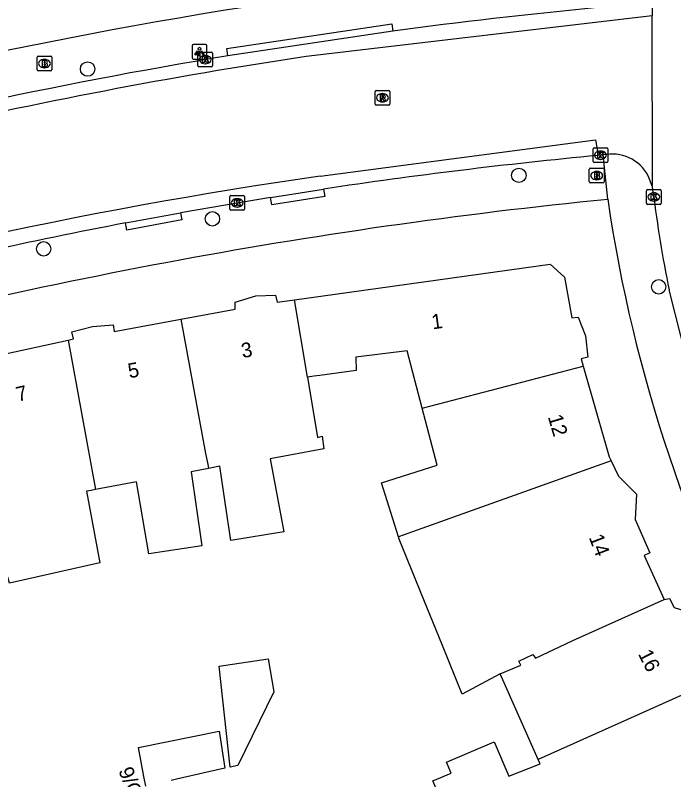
# Model space of a CAD drawing. Extents: x 160356 to 161355, y 381727 to 382845.
# Drawn here: x 161242.7 to 161287.4, y 382329.8 to 382381.7 of the extents above; entities that cross this region are included whole.
import ezdxf

# ---------------------------------------------------------------- set-up
doc = ezdxf.new("R2010")
doc.units = 0
for name, color, linetype in [('IMGEO_Boom', 7, 'Continuous'), ('IMGEO_Brandkraan', 7, 'Continuous'), ('IMGEO_Kolk', 7, 'Continuous'), ('IMGEO_Lichtpunt', 7, 'Continuous'), ('IMGEO_Pand', 7, 'Continuous'), ('IMGEO_Pand_nummerreeks', 7, 'Continuous'), ('IMGEO_Rijbaan_lokaal_open', 7, 'Continuous'), ('IMGEO_Rioolput', 7, 'Continuous'), ('IMGEO_Voetpad_open', 7, 'Continuous')]:
    doc.layers.add(name, color=color, linetype=linetype)

msp = doc.modelspace()

# ---------------------------------------------------------------- linework, layer by layer
at = {"layer": 'IMGEO_Boom'}
for centre in [(161247.634, 382378.019), (161276.877, 382370.816), (161256.1, 382367.867), (161244.655, 382365.834), (161286.356, 382363.259)]:
    msp.add_circle(centre, 0.489, dxfattribs=at)
at = {"layer": 'IMGEO_Brandkraan'}
for p, q in [((161244.282, 382378.894), (161245.134, 382378.894)), ((161244.207, 382377.968), (161244.207, 382378.82)), ((161244.695, 382378.674), (161244.72, 382378.674)), ((161245.208, 382378.82), (161245.208, 382377.968)), ((161245.134, 382377.894), (161244.282, 382377.894)), ((161244.718, 382378.114), (161244.693, 382378.114)), ((161281.654, 382370.372), (161281.654, 382371.224)), ((161281.729, 382371.298), (161282.581, 382371.298)), ((161282.655, 382371.224), (161282.655, 382370.372)), ((161282.142, 382371.078), (161282.167, 382371.078)), ((161282.581, 382370.298), (161281.729, 382370.298)), ((161282.165, 382370.518), (161282.14, 382370.518))]:
    msp.add_line(p, q, dxfattribs=at)
for points in [[(161244.282, 382378.894), (161245.134, 382378.894)], [(161244.207, 382377.968), (161244.207, 382378.82)], [(161244.555, 382378.594), (161244.555, 382378.194), (161244.768, 382378.194)], [(161244.786, 382378.594), (161244.555, 382378.594)], [(161244.734, 382378.513), (161244.68, 382378.513), (161244.68, 382378.437)], [(161244.68, 382378.437), (161244.733, 382378.437)], [(161244.742, 382378.361), (161244.68, 382378.361), (161244.68, 382378.28)], [(161245.208, 382378.82), (161245.208, 382377.968)], [(161245.134, 382377.894), (161244.282, 382377.894)], [(161244.68, 382378.28), (161244.742, 382378.28)], [(161281.654, 382370.372), (161281.654, 382371.224)], [(161281.729, 382371.298), (161282.581, 382371.298)], [(161282.655, 382371.224), (161282.655, 382370.372)], [(161282.002, 382370.998), (161282.002, 382370.598), (161282.215, 382370.598)], [(161282.233, 382370.998), (161282.002, 382370.998)], [(161282.181, 382370.917), (161282.127, 382370.917), (161282.127, 382370.841)], [(161282.127, 382370.841), (161282.18, 382370.841)], [(161282.189, 382370.765), (161282.127, 382370.765), (161282.127, 382370.684)], [(161282.127, 382370.684), (161282.189, 382370.684)], [(161282.581, 382370.298), (161281.729, 382370.298)]]:
    msp.add_lwpolyline(points, dxfattribs=at)
for centre, radius, start, end in [((161244.284, 382378.818), 0.0765, 91.552, 178.448), ((161244.284, 382378.818), 0.0765, 91.552, 178.448), ((161245.132, 382378.818), 0.0765, 1.552, 88.448), ((161245.132, 382378.818), 0.0765, 1.552, 88.448), ((161244.735, 382378.475), 0.0379, 267.8285, 90.9355), ((161244.743, 382378.32), 0.0404, 269.8759, 90.5077), ((161244.79, 382378.449), 0.145, 59.4692, 91.5367), ((161244.815, 382378.496), 0.0922, 285.5137, 58.1501), ((161244.82, 382378.304), 0.105, 301.3115, 78.989), ((161244.284, 382377.97), 0.0765, 181.552, 268.448), ((161244.284, 382377.97), 0.0765, 181.552, 268.448), ((161244.774, 382378.445), 0.251, 268.6676, 293.5347), ((161245.132, 382377.97), 0.0765, 271.552, 358.448), ((161245.132, 382377.97), 0.0765, 271.552, 358.448), ((161281.731, 382371.222), 0.0765, 91.552, 178.448), ((161281.731, 382371.222), 0.0765, 91.552, 178.448), ((161282.579, 382371.222), 0.0765, 1.552, 88.448), ((161282.579, 382371.222), 0.0765, 1.552, 88.448), ((161282.182, 382370.879), 0.0379, 267.8285, 90.9355), ((161282.19, 382370.724), 0.0404, 269.8759, 90.5077), ((161282.221, 382370.849), 0.251, 268.6676, 293.5347), ((161282.237, 382370.853), 0.145, 59.4692, 91.5367), ((161282.262, 382370.9), 0.0922, 285.5137, 58.1501), ((161282.267, 382370.708), 0.105, 301.3115, 78.989), ((161281.731, 382370.374), 0.0765, 181.552, 268.448), ((161281.731, 382370.374), 0.0765, 181.552, 268.448), ((161282.579, 382370.374), 0.0765, 271.552, 358.448), ((161282.579, 382370.374), 0.0765, 271.552, 358.448)]:
    msp.add_arc(centre, radius, start, end, dxfattribs=at)
for centre, major_axis, ratio, start_param, end_param in [((161244.694, 382378.394), (-0.387, 0.002), 0.722429, 4.712389, 7.853982), ((161244.719, 382378.394), (-0.39, 0.002), 0.717154, 1.570796, 4.712389), ((161282.141, 382370.798), (-0.387, 0.002), 0.722429, 4.712389, 7.853982), ((161282.166, 382370.798), (-0.39, 0.002), 0.717154, 1.570796, 4.712389)]:
    msp.add_ellipse(centre, major_axis=major_axis, ratio=ratio, start_param=start_param, end_param=end_param, dxfattribs=at)
at = {"layer": 'IMGEO_Kolk'}
for p, q in [((161255.111, 382378.237), (161255.111, 382379.089)), ((161255.186, 382379.163), (161256.038, 382379.163)), ((161255.599, 382378.943), (161255.624, 382378.943)), ((161256.112, 382379.089), (161256.112, 382378.237)), ((161255.622, 382378.383), (161255.597, 382378.383)), ((161256.038, 382378.163), (161255.186, 382378.163)), ((161281.982, 382372.68), (161282.834, 382372.68)), ((161281.907, 382371.754), (161281.907, 382372.606)), ((161282.395, 382372.46), (161282.42, 382372.46)), ((161282.908, 382372.606), (161282.908, 382371.754)), ((161282.834, 382371.68), (161281.982, 382371.68)), ((161282.418, 382371.9), (161282.393, 382371.9)), ((161285.527, 382368.924), (161285.527, 382369.776)), ((161285.602, 382369.85), (161286.454, 382369.85)), ((161286.015, 382369.63), (161286.04, 382369.63)), ((161286.528, 382369.776), (161286.528, 382368.924)), ((161257.279, 382368.523), (161257.279, 382369.375)), ((161257.354, 382369.449), (161258.206, 382369.449)), ((161257.767, 382369.229), (161257.792, 382369.229)), ((161258.28, 382369.375), (161258.28, 382368.523)), ((161286.038, 382369.07), (161286.013, 382369.07)), ((161257.79, 382368.669), (161257.765, 382368.669)), ((161286.454, 382368.85), (161285.602, 382368.85)), ((161258.206, 382368.449), (161257.354, 382368.449))]:
    msp.add_line(p, q, dxfattribs=at)
for points in [[(161255.111, 382378.237), (161255.111, 382379.089)], [(161255.186, 382379.163), (161256.038, 382379.163)], [(161256.112, 382379.089), (161256.112, 382378.237)], [(161255.432, 382378.863), (161255.555, 382378.863), (161255.555, 382378.712), (161255.685, 382378.863), (161255.849, 382378.863), (161255.703, 382378.712), (161255.856, 382378.463), (161255.704, 382378.463), (161255.619, 382378.627), (161255.555, 382378.56), (161255.555, 382378.463), (161255.432, 382378.463), (161255.432, 382378.863)], [(161256.038, 382378.163), (161255.186, 382378.163)], [(161281.982, 382372.68), (161282.834, 382372.68)], [(161281.907, 382371.754), (161281.907, 382372.606)], [(161282.228, 382372.38), (161282.351, 382372.38), (161282.351, 382372.229), (161282.481, 382372.38), (161282.645, 382372.38), (161282.499, 382372.229), (161282.652, 382371.98), (161282.5, 382371.98), (161282.415, 382372.144), (161282.351, 382372.077), (161282.351, 382371.98), (161282.228, 382371.98), (161282.228, 382372.38)], [(161282.908, 382372.606), (161282.908, 382371.754)], [(161282.834, 382371.68), (161281.982, 382371.68)], [(161285.527, 382368.924), (161285.527, 382369.776)], [(161285.602, 382369.85), (161286.454, 382369.85)], [(161285.848, 382369.55), (161285.971, 382369.55), (161285.971, 382369.399), (161286.101, 382369.55), (161286.265, 382369.55), (161286.119, 382369.399), (161286.272, 382369.15), (161286.12, 382369.15), (161286.035, 382369.314), (161285.971, 382369.247), (161285.971, 382369.15), (161285.848, 382369.15), (161285.848, 382369.55)], [(161286.528, 382369.776), (161286.528, 382368.924)], [(161257.279, 382368.523), (161257.279, 382369.375)], [(161257.354, 382369.449), (161258.206, 382369.449)], [(161257.6, 382369.149), (161257.723, 382369.149), (161257.723, 382368.998), (161257.853, 382369.149), (161258.017, 382369.149), (161257.871, 382368.998), (161258.024, 382368.749), (161257.872, 382368.749), (161257.787, 382368.913), (161257.723, 382368.846), (161257.723, 382368.749), (161257.6, 382368.749), (161257.6, 382369.149)], [(161258.28, 382369.375), (161258.28, 382368.523)], [(161286.454, 382368.85), (161285.602, 382368.85)], [(161258.206, 382368.449), (161257.354, 382368.449)]]:
    msp.add_lwpolyline(points, dxfattribs=at)
for centre, start, end in [((161255.188, 382379.087), 91.552, 178.448), ((161255.188, 382379.087), 91.552, 178.448), ((161256.036, 382379.087), 1.552, 88.448), ((161256.036, 382379.087), 1.552, 88.448), ((161255.188, 382378.239), 181.552, 268.448), ((161255.188, 382378.239), 181.552, 268.448), ((161256.036, 382378.239), 271.552, 358.448), ((161256.036, 382378.239), 271.552, 358.448), ((161281.984, 382372.604), 91.552, 178.448), ((161281.984, 382372.604), 91.552, 178.448), ((161282.832, 382372.604), 1.552, 88.448), ((161282.832, 382372.604), 1.552, 88.448), ((161281.984, 382371.756), 181.552, 268.448), ((161281.984, 382371.756), 181.552, 268.448), ((161282.832, 382371.756), 271.552, 358.448), ((161282.832, 382371.756), 271.552, 358.448), ((161285.604, 382369.774), 91.552, 178.448), ((161285.604, 382369.774), 91.552, 178.448), ((161286.452, 382369.774), 1.552, 88.448), ((161286.452, 382369.774), 1.552, 88.448), ((161257.356, 382369.373), 91.552, 178.448), ((161257.356, 382369.373), 91.552, 178.448), ((161258.204, 382369.373), 1.552, 88.448), ((161258.204, 382369.373), 1.552, 88.448), ((161257.356, 382368.525), 181.552, 268.448), ((161257.356, 382368.525), 181.552, 268.448), ((161258.204, 382368.525), 271.552, 358.448), ((161258.204, 382368.525), 271.552, 358.448), ((161285.604, 382368.926), 181.552, 268.448), ((161285.604, 382368.926), 181.552, 268.448), ((161286.452, 382368.926), 271.552, 358.448), ((161286.452, 382368.926), 271.552, 358.448)]:
    msp.add_arc(centre, 0.0765, start, end, dxfattribs=at)
for centre, major_axis, ratio, start_param, end_param in [((161255.598, 382378.663), (-0.387, 0.002), 0.722429, 4.712389, 7.853982), ((161255.623, 382378.663), (-0.39, 0.002), 0.717154, 1.570796, 4.712389), ((161282.394, 382372.18), (-0.387, 0.002), 0.722429, 4.712389, 7.853982), ((161282.419, 382372.18), (-0.39, 0.002), 0.717154, 1.570796, 4.712389), ((161286.014, 382369.35), (-0.387, 0.002), 0.722429, 4.712389, 7.853982), ((161286.039, 382369.35), (-0.39, 0.002), 0.717154, 1.570796, 4.712389), ((161257.766, 382368.949), (-0.387, 0.002), 0.722429, 4.712389, 7.853982), ((161257.791, 382368.949), (-0.39, 0.002), 0.717154, 1.570796, 4.712389)]:
    msp.add_ellipse(centre, major_axis=major_axis, ratio=ratio, start_param=start_param, end_param=end_param, dxfattribs=at)
at = {"layer": 'IMGEO_Lichtpunt'}
for p, q in [((161254.722, 382379.6), (161254.722, 382378.793)), ((161254.722, 382379.6), (161254.722, 382378.793)), ((161255.624, 382379.695), (161254.816, 382379.695)), ((161255.624, 382379.695), (161254.816, 382379.695)), ((161255.718, 382378.793), (161255.718, 382379.6)), ((161255.718, 382378.793), (161255.718, 382379.6)), ((161254.816, 382378.699), (161255.624, 382378.699)), ((161254.816, 382378.699), (161255.624, 382378.699))]:
    msp.add_line(p, q, dxfattribs=at)
for points in [[(161255.096, 382379.264), (161255.135, 382379.236), (161254.947, 382378.974), (161254.909, 382379.001), (161255.096, 382379.264)], [(161255.198, 382379.216), (161255.245, 382379.216), (161255.245, 382378.894), (161255.198, 382378.894), (161255.198, 382379.216)], [(161255.308, 382379.236), (161255.346, 382379.263), (161255.533, 382379.001), (161255.494, 382378.973), (161255.308, 382379.236)]]:
    msp.add_lwpolyline(points, dxfattribs=at)
msp.add_circle((161255.221, 382379.398), 0.0994, dxfattribs=at)
for centre, start, end in [((161254.816, 382379.6), 90, 180), ((161254.816, 382379.6), 90, 180), ((161255.624, 382379.6), 0, 90), ((161255.624, 382379.6), 0, 90), ((161254.816, 382378.793), 180, 270), ((161254.816, 382378.793), 180, 270), ((161255.624, 382378.793), 270, 0), ((161255.624, 382378.793), 270, 360)]:
    msp.add_arc(centre, 0.0946, start, end, dxfattribs=at)
at = {"layer": 'IMGEO_Pand'}
for points in [[(161261.673, 382362.386), (161278.988, 382364.789), (161279.97, 382363.923), (161280.478, 382361.165), (161280.908, 382361.206), (161281.391, 382359.928), (161281.556, 382358.489), (161281.096, 382358.387), (161281.244, 382357.87)], [(161253.95, 382361.072), (161257.643, 382361.754), (161257.632, 382362.223), (161259.04, 382362.648), (161260.369, 382362.702), (161260.491, 382362.222), (161261.673, 382362.386)], [(161262.547, 382357.134), (161261.673, 382362.386)], [(161246.318, 382359.651), (161246.683, 382359.73), (161246.561, 382360.209), (161247.969, 382360.574), (161249.369, 382360.678), (161249.43, 382360.238), (161253.95, 382361.072)], [(161253.95, 382361.072), (161255.629, 382351.97), (161255.737, 382351.446), (161255.81, 382351.097), (161255.84, 382350.949)], [(161238.514, 382357.78), (161239.25, 382357.986), (161239.497, 382358.966), (161241.156, 382359.372), (161242.147, 382358.745), (161246.318, 382359.651)], [(161246.318, 382359.651), (161248.18, 382349.514)], [(161270.321, 382355.031), (161269.296, 382358.918), (161265.831, 382358.48), (161265.834, 382357.588), (161263.391, 382357.251), (161262.966, 382357.192), (161262.547, 382357.134)], [(161270.321, 382355.031), (161281.244, 382357.87)], [(161281.244, 382357.87), (161283.005, 382351.725), (161283.129, 382351.469)], [(161262.547, 382357.134), (161263.227, 382353.046), (161263.539, 382353.132), (161263.66, 382352.275), (161260.024, 382351.593), (161260.938, 382346.647), (161257.351, 382346.067), (161256.963, 382348.635), (161256.592, 382351.09), (161255.84, 382350.949)], [(161268.715, 382346.308), (161267.556, 382349.968), (161271.342, 382351.159), (161270.321, 382355.031)], [(161283.129, 382351.469), (161268.715, 382346.308)], [(161283.129, 382351.469), (161283.639, 382350.417), (161284.843, 382349.201), (161284.769, 382347.481), (161285.755, 382345.215), (161285.366, 382345.044), (161286.734, 382342.07)], [(161255.84, 382350.949), (161254.651, 382350.726), (161254.994, 382348.369), (161255.382, 382345.701), (161251.795, 382345.159), (161250.961, 382350.035), (161248.18, 382349.514)], [(161248.18, 382349.514), (161247.873, 382349.457), (161247.569, 382349.4), (161248.458, 382344.557), (161242.337, 382343.165), (161242.22, 382343.587)], [(161275.603, 382337.026), (161273.041, 382335.642), (161271.694, 382338.953), (161270.438, 382342.037), (161268.768, 382346.142), (161268.715, 382346.308)], [(161286.734, 382342.07), (161287.094, 382342.13), (161287.405, 382341.521), (161288.136, 382341.304), (161289.071, 382339.287), (161288.674, 382338.636), (161289.652, 382336.355)], [(161275.603, 382337.026), (161277.011, 382337.6), (161276.87, 382337.89), (161277.819, 382338.323), (161278.009, 382338.083), (161280.531, 382339.275), (161286.734, 382342.07)], [(161256.553, 382337.552), (161259.867, 382338.051), (161260.252, 382335.804), (161257.823, 382330.805), (161257.291, 382330.695), (161256.553, 382337.552)], [(161278.18, 382331.222), (161275.603, 382337.026)], [(161289.652, 382336.355), (161278.18, 382331.222)], [(161251.574, 382329.407), (161251.451, 382330.062), (161251.08, 382332.04), (161256.547, 382333.131), (161256.932, 382330.621), (161253.655, 382329.881), (161253.299, 382329.801)], [(161277.614, 382322.834), (161275.593, 382327.259), (161274.999, 382328.457), (161273.282, 382327.882), (161272.98, 382328.605), (161271.752, 382328.117), (161271.037, 382329.774), (161272.279, 382330.292), (161271.973, 382331.027), (161275.208, 382332.406), (161276.194, 382330.08), (161278.311, 382330.926), (161278.18, 382331.222)]]:
    msp.add_lwpolyline(points, dxfattribs=at)
at = {"layer": 'IMGEO_Rijbaan_lokaal_open'}
for points in [[(161285.895, 382385.129), (161285.905, 382381.624)], [(161285.905, 382381.624), (161262.449, 382378.874)], [(161285.941, 382370.048), (161285.905, 382381.624)], [(161263.413, 382370.769), (161282.072, 382373.222), (161282.249, 382372.166)], [(161282.584, 382372.198), (161282.249, 382372.166)], [(161285.941, 382370.048), (161285.644, 382370.777)], [(161285.992, 382369.658), (161285.941, 382370.048)], [(161298.994, 382332.13), (161297.539, 382335.546), (161295.93, 382339.49), (161293.77, 382344.297), (161293.217, 382345.548), (161292.55, 382347.123), (161291.766, 382348.825), (161290.242, 382352.118), (161289.151, 382355.236), (161288.259, 382358.335), (161287.062, 382363.053)]]:
    msp.add_lwpolyline(points, dxfattribs=at)
for centre, radius, start, end in [((161315.008, 382030.634), 352.184, 98.58267, 107.61259), ((161283.184, 382369.484), 2.78, 27.7242, 102.4574), ((161311.029, 382041.68), 332.516, 98.23294, 106.70012), ((161365.467, 382379.144), 80.039, 186.80628, 191.5975)]:
    msp.add_arc(centre, radius, start, end, dxfattribs=at)
at = {"layer": 'IMGEO_Rioolput'}
for p, q in [((161267.127, 382375.652), (161267.127, 382376.504)), ((161267.202, 382376.578), (161268.054, 382376.578)), ((161267.615, 382376.358), (161267.64, 382376.358)), ((161268.128, 382376.504), (161268.128, 382375.652)), ((161267.638, 382375.798), (161267.613, 382375.798)), ((161268.054, 382375.578), (161267.202, 382375.578))]:
    msp.add_line(p, q, dxfattribs=at)
for points in [[(161267.127, 382375.652), (161267.127, 382376.504)], [(161267.202, 382376.578), (161268.054, 382376.578)], [(161267.716, 382376.276), (161267.464, 382376.278), (161267.464, 382375.878)], [(161268.128, 382376.504), (161268.128, 382375.652)], [(161267.464, 382375.878), (161267.588, 382375.878), (161267.588, 382376.04), (161267.599, 382376.04)], [(161267.642, 382376.197), (161267.588, 382376.197), (161267.588, 382376.116)], [(161267.588, 382376.116), (161267.64, 382376.116)], [(161267.646, 382376.011), (161267.717, 382375.878), (161267.857, 382375.878), (161267.792, 382376.004)], [(161268.054, 382375.578), (161267.202, 382375.578)]]:
    msp.add_lwpolyline(points, dxfattribs=at)
for centre, radius, start, end in [((161267.204, 382376.502), 0.0765, 91.552, 178.448), ((161267.204, 382376.502), 0.0765, 91.552, 178.448), ((161268.052, 382376.502), 0.0765, 1.552, 88.448), ((161268.052, 382376.502), 0.0765, 1.552, 88.448), ((161267.598, 382375.987), 0.0533, 26.0293, 88.6989), ((161267.624, 382376.305), 0.19, 274.7715, 282.9687), ((161267.648, 382376.101), 0.0964, 77.0061, 93.1865), ((161267.662, 382376.158), 0.0378, 276.6634, 79.6772), ((161267.715, 382376.166), 0.109, 350.3612, 89.416), ((161267.713, 382376.166), 0.112, 277.5842, 350.9817), ((161267.697, 382375.951), 0.108, 29.5134, 73.7905), ((161267.204, 382375.654), 0.0765, 181.552, 268.448), ((161267.204, 382375.654), 0.0765, 181.552, 268.448), ((161268.052, 382375.654), 0.0765, 271.552, 358.448), ((161268.052, 382375.654), 0.0765, 271.552, 358.448)]:
    msp.add_arc(centre, radius, start, end, dxfattribs=at)
for centre, major_axis, ratio, start_param, end_param in [((161267.614, 382376.078), (-0.387, 0.002), 0.722429, 4.712389, 7.853982), ((161267.639, 382376.078), (-0.39, 0.002), 0.717154, 1.570796, 4.712389)]:
    msp.add_ellipse(centre, major_axis=major_axis, ratio=ratio, start_param=start_param, end_param=end_param, dxfattribs=at)
at = {"layer": 'IMGEO_Voetpad_open'}
for points in [[(161257.145, 382378.919), (161257.074, 382379.413), (161268.253, 382381.09), (161268.324, 382380.596)], [(161268.324, 382380.596), (161257.145, 382378.919)], [(161282.903, 382369.19), (161282.584, 382372.198)], [(161263.637, 382369.883), (161263.712, 382369.389), (161260.115, 382368.828), (161260.04, 382369.322)], [(161260.04, 382369.322), (161263.637, 382369.883)], [(161260.04, 382369.322), (161253.941, 382368.282)], [(161253.941, 382368.282), (161254.03, 382367.79), (161250.302, 382367.099), (161250.213, 382367.591)], [(161250.213, 382367.591), (161253.941, 382368.282)]]:
    msp.add_lwpolyline(points, dxfattribs=at)
for centre, radius, start, end in [((161313.862, 382031.297), 355.29, 98.98975, 114.75287), ((161316.369, 382022.129), 361.672, 95.45404, 97.6338), ((161316.417, 382021.837), 361.967, 99.42453, 110.77806), ((161314.579, 382031.59), 342.107, 95.42269, 98.56357), ((161318.044, 382017.574), 353.367, 95.70735, 105.52358), ((161381.976, 382383.685), 100.128, 188.32347, 208.82203), ((161314.622, 382030.708), 342.985, 100.82386, 104.10792)]:
    msp.add_arc(centre, radius, start, end, dxfattribs=at)

# ---------------------------------------------------------------- texts
at = {"layer": 'IMGEO_Pand_nummerreeks'}
for s, rotation, p in [('1', 7.9011, (161271.023, 382360.373)), ('3', 10.1012, (161258.139, 382358.425)), ('5', 10.1012, (161250.461, 382357.057)), ('7', 13.476, (161242.913, 382355.461)), ('12', 286.4077, (161278.832, 382354.452)), ('14', 290.9815, (161281.606, 382346.282)), ('16', 297.0532, (161284.937, 382338.376)), ('9/G01', 291.5487, (161249.707, 382330.474))]:
    msp.add_text(s, height=1, rotation=rotation, dxfattribs=at).set_placement(p)

doc.saveas('drawing.dxf')
